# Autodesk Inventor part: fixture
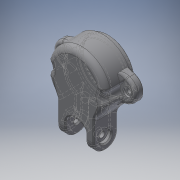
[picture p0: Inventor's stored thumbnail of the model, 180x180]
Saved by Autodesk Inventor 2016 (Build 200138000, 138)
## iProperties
Created: 2015-05
Part Number: fixture
Material: Generic
Document SubType Name: Modeling
Designer: Brent
Density: 1 g/cm^3
Appearance: Default
Author: Brent
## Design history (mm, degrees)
sketch "Sketch1"
  geometry: C1 r 1.714 at (-18.088, 0) reference; C2 r 1.714 at (17.994, 0) reference; C3 r 15.082 at (0, 0) reference; C4 r 1.207 at (17.994, 0) reference; C5 r 1.207 at (-18.088, 0) reference; C6 r 14.574 at (0, 0) reference; C7 r 12.839 at (0, 0) reference; C8 r 12.331 at (0, 0) reference; A1 r 15.891 centre (0, 0) between (-13.931, -7.644) and (13.931, -7.644) reference; A2 r 6.705 centre (15.686, 0) between (17.796, -6.365) and (17.796, 6.365) reference; A3 r 15.891 centre (0, 0) between (13.931, 7.644) and (-13.931, 7.644) reference; A4 r 6.705 centre (-15.686, 0) between (-17.796, 6.365) and (-17.796, -6.365) reference; 1 further point
extrude "Extrusion1" new body sketch "Sketch1" distance "d0" = 1.5875; taper "d1" = 0 deg
chamfer "Chamfer1" distance "d2" = 0.508; stored, may be unused: second distance "d3" = 3.175, angle "d4" = 45 deg
chamfer "Chamfer2" distance "d5" = 0.508; stored, may be unused: second distance "d6" = 3.175, angle "d7" = 45 deg
sketch "Sketch2"
  geometry: C1 r 12.997 at (0, 0); C2 r 14.443 at (0, 0); 1 further point
  constraints: 2 centre point, 2 coincident
extrude "Extrusion2" join sketch "Sketch2" distance "d8" = 3.048; taper "d9" = 0 deg
chamfer "Chamfer3" distance "d10" = 0.254; stored, may be unused: second distance "d11" = 3.048, angle "d12" = 45 deg
chamfer "Chamfer4" distance "d13" = 0.254; stored, may be unused: second distance "d14" = 3.048, angle "d15" = 45 deg
chamfer "Chamfer5" distance "d16" = 0.254; stored, may be unused: second distance "d17" = 3.048, angle "d18" = 45 deg
sketch "Sketch3"
  geometry: L1 (9.753, -12.545)-(9.753, -29.702); L2 (9.753, -29.702)-(5.352, -29.702); L3 (5.352, -29.702)-(5.352, -14.962); L4 (-9.899, -12.431)-(-9.899, -29.702); L5 (-9.899, -29.702)-(-5.569, -29.702); L6 (-5.569, -29.702)-(-5.569, -14.883); C1 r 12.331 at (0, 0) reference; C2 r 1.207 at (17.994, 0) reference; C3 r 1.207 at (-18.088, 0) reference; C4 r 12.331 at (0, 0) reference; A1 r 15.891 centre (0, 0) between (-13.931, -7.644) and (13.931, -7.644) reference; A2 r 6.705 centre (15.686, 0) between (17.796, -6.365) and (17.796, 6.365) reference; A3 r 15.891 centre (0, 0) between (13.931, 7.644) and (-13.931, 7.644) reference; A4 r 6.705 centre (-15.686, 0) between (-17.796, 6.365) and (-17.796, -6.365) reference; 1 further point
  constraints: 12 end point, 4 point on circle, 2 parallel, 1 point on line, 4 other
extrude "Extrusion3" join sketch "Sketch3" distance "d19" = 3.048; taper "d20" = 0 deg
sketch "Sketch4"
  geometry: L1 (-9.899, -29.702)-(-5.569, -29.702) reference; L2 (-5.569, -29.702)-(-5.569, -14.883) reference; L3 (5.352, -14.962)-(5.352, -29.702) reference; L4 (5.352, -29.702)-(9.753, -29.702) reference; L5 (9.753, -29.702)-(9.753, -12.545) reference; L6 (-9.899, -12.431)-(-9.899, -29.702) reference; C1 r 12.331 at (0, 0) reference; C2 r 1.207 at (-18.088, 0) reference; C3 r 1.207 at (17.994, 0) reference; C4 r 15.891 at (0, 0); A1 r 15.891 centre (0, 0) between (-5.569, -14.883) and (5.352, -14.962) reference; A2 r 15.891 centre (0, 0) between (9.753, -12.545) and (13.931, -7.644) reference; A3 r 6.705 centre (15.686, 0) between (17.796, -6.365) and (17.796, 6.365) reference; A4 r 15.891 centre (0, 0) between (13.931, 7.644) and (-13.931, 7.644) reference; A5 r 6.705 centre (-15.686, 0) between (-17.796, 6.365) and (-17.796, -6.365) reference; A6 r 15.891 centre (0, 0) between (-13.931, -7.644) and (-9.899, -12.431) reference; 1 further point
  constraints: 1 centre point, 1 coincident, 4 other
extrude "Extrusion4" join sketch "Sketch4" distance "d21" = 6.223; taper "d22" = 0 deg
sketch "Sketch5"
  geometry: L1 (-9.899, -12.431)-(-9.899, -29.702) reference; L2 (-9.899, -29.702)-(-5.569, -29.702) reference; L3 (-5.569, -29.702)-(-5.569, -14.883) reference; L4 (5.352, -14.962)-(5.352, -29.702) reference; L5 (5.352, -29.702)-(9.753, -29.702) reference; L6 (9.753, -29.702)-(9.753, -12.545) reference; A1 r 15.891 centre (0, 0) between (-9.899, -12.431) and (-5.569, -14.883) reference; A2 r 15.891 centre (0, 0) between (5.352, -14.962) and (9.753, -12.545) reference; 1 further point
extrude "Extrusion5" join sketch "Sketch5" distance "d23" = 6.223; taper "d24" = 0 deg
sketch "Sketch6"
  geometry: C1 r 1.207 at (17.994, 0) reference; C2 r 1.207 at (-18.088, 0) reference; C3 r 3.89 at (17.994, 0); C4 r 1.207 at (-18.088, 0) reference; C5 r 3.89 at (-18.088, 0); A1 r 15.891 centre (0, 0) between (13.931, -7.644) and (13.931, 7.644) reference; A2 r 6.705 centre (15.686, 0) between (17.796, -6.365) and (17.796, 6.365) reference; A3 r 15.891 centre (0, 0) between (-13.931, 7.644) and (-13.931, -7.644) reference; A4 r 6.705 centre (-15.686, 0) between (-17.796, 6.365) and (-17.796, -6.365) reference; 1 further point
  constraints: 2 centre point, 2 coincident, 4 other
extrude "Extrusion6" cut sketch "Sketch6" distance "d25" = 6.223; taper "d26" = 0 deg
fillet "Fillet1" dims "d27" = 1.5875
sketch "Sketch7"
  geometry: C1 r 1.207 at (-18.088, 0) reference; C2 r 1.207 at (17.994, 0) reference; C3 r 2.376 at (-18.088, 0); C4 r 2.376 at (17.994, 0); A1 r 17.478 centre (0, 0) between (-17.07, -3.754) and (-16.734, -5.044) reference; A2 r 3.89 centre (-18.088, 0) between (-17.07, -3.754) and (-17.07, 3.754) reference; A3 r 17.478 centre (0, 0) between (-16.734, 5.044) and (-17.07, 3.754) reference; A4 r 5.118 centre (-15.686, 0) between (-17.296, 4.858) and (-17.296, -4.858) reference; A5 r 17.478 centre (0, 0) between (17.065, 3.777) and (16.734, 5.044) reference; A6 r 3.89 centre (17.994, 0) between (17.065, 3.777) and (17.065, -3.777) reference; A7 r 17.478 centre (0, 0) between (16.734, -5.044) and (17.065, -3.777) reference; A8 r 5.118 centre (15.686, 0) between (17.296, -4.858) and (17.296, 4.858) reference; 1 further point
  constraints: 2 centre point, 2 coincident, 4 other
extrude "Extrusion7" cut sketch "Sketch7" distance "d28" = 1.016; taper "d29" = 0 deg
fillet "Fillet2" dims "d30" = 1.5875
sketch "Sketch8"
  geometry: L1 (-9.899, -12.431)-(-9.899, -29.702) reference; L2 (-9.899, -29.702)-(-5.569, -29.702) reference; L3 (-5.569, -29.702)-(-5.569, -14.883) reference; L4 (5.352, -14.962)-(5.352, -29.702) reference; L5 (5.352, -29.702)-(9.753, -29.702) reference; L6 (9.753, -29.702)-(9.753, -12.545) reference; L7 (-5.569, -29.702)-(-5.569, -14.883) reference; L8 (-5.569, -19.842)-(5.352, -19.842); L9 (5.352, -19.842)-(5.352, -7.782); L10 (5.352, -7.782)-(-5.569, -7.782); L11 (-5.569, -7.782)-(-5.569, -19.842); C1 r 12.331 at (0, 0) reference; A1 r 1.588 centre (-13.87, 3.494) between (-15.409, 3.881) and (-15.092, 2.481) reference; A2 r 3.89 centre (-18.088, 0) between (-15.092, -2.481) and (-15.092, 2.481) reference; A3 r 1.587 centre (-13.87, -3.494) between (-15.092, -2.481) and (-15.409, -3.881) reference; A4 r 15.891 centre (0, 0) between (-15.409, -3.881) and (-9.899, -12.431) reference; A5 r 15.891 centre (0, 0) between (-5.569, -14.883) and (5.352, -14.962) reference; A6 r 15.891 centre (0, 0) between (9.753, -12.545) and (15.385, -3.976) reference; A7 r 1.587 centre (13.848, -3.579) between (15.385, -3.976) and (15.05, -2.541) reference; A8 r 3.89 centre (17.994, 0) between (15.05, 2.541) and (15.05, -2.541) reference; A9 r 1.587 centre (13.848, 3.579) between (15.05, 2.541) and (15.385, 3.976) reference; A10 r 15.891 centre (0, 0) between (15.385, 3.976) and (-15.409, 3.881) reference; 1 further point
  constraints: 8 end point, 2 parallel, 1 horizontal, 1 perpendicular, 1 point on line
extrude "Extrusion8" cut sketch "Sketch8" distance "d31" = 6.9215; taper "d32" = 0 deg
sketch "Sketch9"
  geometry: L1 (5.352, -11.109)-(5.352, -29.702) reference; L2 (5.352, -29.702)-(9.753, -29.702) reference; L3 (9.753, -29.702)-(9.753, -12.545) reference; L4 (-9.899, -12.431)-(-9.899, -29.702) reference; L5 (-9.899, -29.702)-(-5.569, -29.702) reference; L6 (-5.569, -29.702)-(-5.569, -11.001) reference; L7 (-9.899, -29.702)-(-5.569, -29.702) reference; L8 (-9.899, -29.702)-(9.753, -29.702); L9 (9.753, -29.702)-(9.753, -12.545); L10 (9.753, -12.545)-(-9.899, -12.545); L11 (-9.899, -12.545)-(-9.899, -29.702); C1 r 12.331 at (0, 0); A1 r 15.891 centre (0, 0) between (9.753, -12.545) and (15.385, -3.976) reference; A2 r 1.587 centre (13.848, -3.579) between (15.385, -3.976) and (15.05, -2.541) reference; A3 r 3.89 centre (17.994, 0) between (15.05, 2.541) and (15.05, -2.541) reference; A4 r 1.587 centre (13.848, 3.579) between (15.05, 2.541) and (15.385, 3.976) reference; A5 r 15.891 centre (0, 0) between (15.385, 3.976) and (-15.409, 3.881) reference; A6 r 1.588 centre (-13.87, 3.494) between (-15.409, 3.881) and (-15.092, 2.481) reference; A7 r 3.89 centre (-18.088, 0) between (-15.092, -2.481) and (-15.092, 2.481) reference; A8 r 1.587 centre (-13.87, -3.494) between (-15.092, -2.481) and (-15.409, -3.881) reference; A9 r 15.891 centre (0, 0) between (-15.409, -3.881) and (-9.899, -12.431) reference; A10 r 12.331 centre (0, 0) between (5.352, -11.109) and (-5.569, -11.001) reference; A11 r 15.891 centre (0, 0) between (-15.409, -3.881) and (15.385, -3.976); A12 r 15.891 centre (0, 0) between (15.385, 3.976) and (-15.409, 3.881); 1 further point
  constraints: 8 end point, 8 point on circle, 3 centre point, 2 coincident, 2 parallel, 1 horizontal, 1 perpendicular
extrude "Extrusion9" join sketch "Sketch9" distance "d33" = 3.7465; taper "d34" = 0 deg
fillet "Fillet3" dims "d35" = 3.175
fillet "Fillet4" dims "d36" = 6.35
sketch "Sketch10"
  geometry: L1 (9.842, -10.807)-(9.842, 0) reference; L2 (9.842, 0)-(0, 0) reference; L3 (-3.175, -10.807)-(-3.175, 4.387) reference; L4 (3.492, -17.157)-(3.175, -17.157) reference; C1 r 1.524 at (3.334, -10.807); A1 r 6.35 centre (3.492, -10.807) between (3.492, -17.157) and (9.842, -10.807) reference; A2 r 6.35 centre (3.175, -10.807) between (-3.175, -10.807) and (3.175, -17.157) reference; 1 further point
  constraints: 1 centre point, 1 other
  dimensions: "d37" = 3.048 diameter of C1
extrude "Extrusion10" cut sketch "Sketch10" distance "d38" = 28.0035; taper "d39" = 0 deg
sketch "Sketch11"
  geometry: L1 (-5.569, -29.144)-(-5.569, -11.001) reference; L2 (5.352, -11.109)-(5.352, -29.144) reference; L3 (-5.569, -29.144)-(5.352, -29.144) reference; L4 (-5.569, -23.352)-(-5.569, -14.883) reference; L5 (-5.569, -19.762)-(-5.569, -32.454); L6 (-5.569, -32.454)-(5.352, -32.454); L7 (5.352, -32.454)-(5.352, -19.713); A1 r 7.59 centre (-0.085, -25.008) between (5.352, -19.713) and (-5.569, -19.762); 3 further points
  constraints: 6 end point, 3 point on line, 2 point on circle, 1 centre point, 1 collinear, 1 perpendicular
extrude "Extrusion11" cut sketch "Sketch11" distance "d40" = 6.9215; taper "d41" = 0 deg
fillet "Fillet5" dims "d42" = 1.5875
fillet "Fillet6" dims "d43" = 2.159
fillet "Fillet7" dims "d44" = 2.159
fillet "Fillet8" dims "d45" = 2.159
sketch "Sketch12"
  geometry: C1 r 1.524 at (3.334, -9.792) reference; C2 r 1.524 at (3.334, -9.792) reference; C3 r 3.175 at (3.334, -9.792); 1 further point
  constraints: 1 centre point, 1 coincident
  dimensions: "d49" = 6.35 diameter of C3
extrude "Extrusion12" cut sketch "Sketch12" distance "d50" = 2.032; taper "d51" = 0 deg
chamfer "Chamfer7" distance "d52" = 0.635; stored, may be unused: second distance "d53" = 3.048, angle "d54" = 45 deg
chamfer "Chamfer8" distance "d55" = 0.635; stored, may be unused: second distance "d56" = 3.048, angle "d57" = 45 deg
sketch "Sketch13"
  geometry: L1 (-0.517, 0)-(9.751, 0) reference; L2 (6.418, -9.92)-(6.418, -13.095); L3 (4.585, -13.095)-(2.752, -9.92); L4 (2.752, -9.92)-(4.585, -6.745); L5 (4.585, -6.745)-(8.251, -6.745); L6 (8.251, -6.745)-(10.084, -9.92); L7 (10.084, -9.92)-(8.251, -13.095); L8 (8.251, -13.095)-(4.585, -13.095); L9 (-0.091, -1.57)-(-0.091, -9.92) reference; L10 (6.259, -16.27)-(6.576, -16.27) reference; L11 (12.926, -9.92)-(12.926, 1.445) reference; C1 r 1.524 at (6.418, -9.92) reference; C2 r 1.524 at (6.418, -9.92) reference; A1 r 6.35 centre (6.259, -9.92) between (-0.091, -9.92) and (6.259, -16.27) reference; A2 r 6.35 centre (6.576, -9.92) between (6.576, -16.27) and (12.926, -9.92) reference; 2 further points
  constraints: 14 end point, 1 coincident, 1 midpoint, 1 vertical, 15 other
  dimensions: "d58" = 3.175 distance of L2.start L2.end
extrude "Extrusion13" cut sketch "Sketch13" distance "d59" = 2.032; taper "d60" = 0 deg
chamfer "Chamfer9" distance "d61" = 0.635; stored, may be unused: second distance "d62" = 3.048, angle "d63" = 45 deg
chamfer "Chamfer10" distance "d64" = 0.254; stored, may be unused: second distance "d65" = 3.048, angle "d66" = 45 deg
sketch "Sketch14"
  geometry: L1 (5.569, -17.65)-(5.569, -11.001) reference; L2 (-5.352, -11.109)-(-5.352, -17.615) reference; L3 (-5.352, -11.109)-(-5.352, -9.56); L4 (-5.352, -13.942)-(-3.193, -13.942) reference; L5 (5.569, -11.001)-(5.569, -9.435); C1 r 12.331 at (0, 0) reference; A1 r 10.956 centre (0, 0) between (-5.352, -9.56) and (5.569, -9.435); A2 r 9.177 centre (0.085, -25.008) between (5.569, -17.65) and (-5.352, -17.615) reference; A3 r 12.331 centre (0, 0) between (5.569, -11.001) and (-5.352, -11.109) reference; 1 further point
  constraints: 4 end point, 2 point on circle, 1 centre point, 1 coincident, 1 parallel, 1 perpendicular
extrude "Extrusion14" join sketch "Sketch14" distance "d67" = 9.144; taper "d68" = 0 deg
fillet "Fillet9" dims "d69" = 2.159
chamfer "Chamfer11" distance "d70" = 0.635; stored, may be unused: second distance "d71" = 3.048, angle "d72" = 45 deg
body "Solid1"
node "Reference1"
node "Reference2"
node "Reference3"
node "Reference4"
node "Reference5"
node "Reference6"
node "Projected Loop1"
node "Projected Loop2"
node "Projected Loop3"
node "Projected Loop4"
node "Projected Loop5"
node "Projected Loop6"
node "Projected Loop7"
node "Projected Loop8"
node "Projected Loop9"
node "Projected Loop10"
node "Projected Loop11"
node "Projected Loop12"
node "Projected Loop13"
